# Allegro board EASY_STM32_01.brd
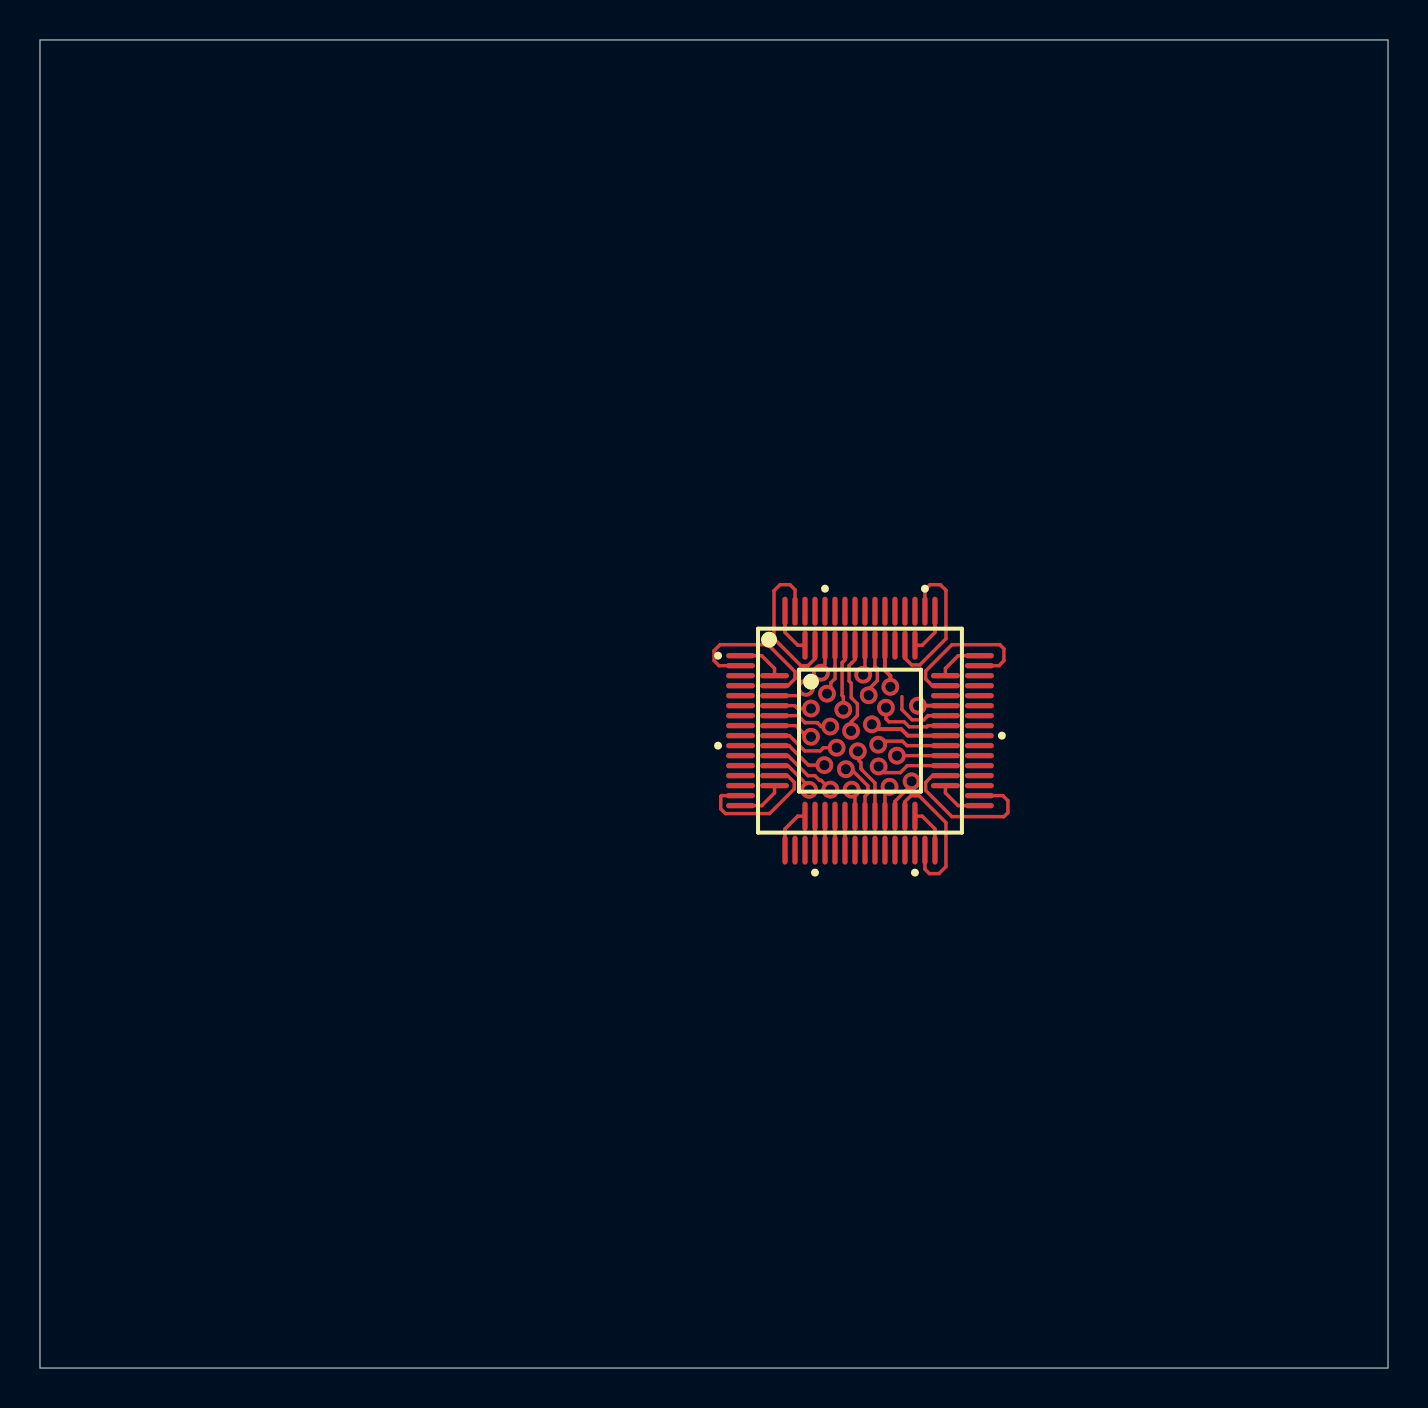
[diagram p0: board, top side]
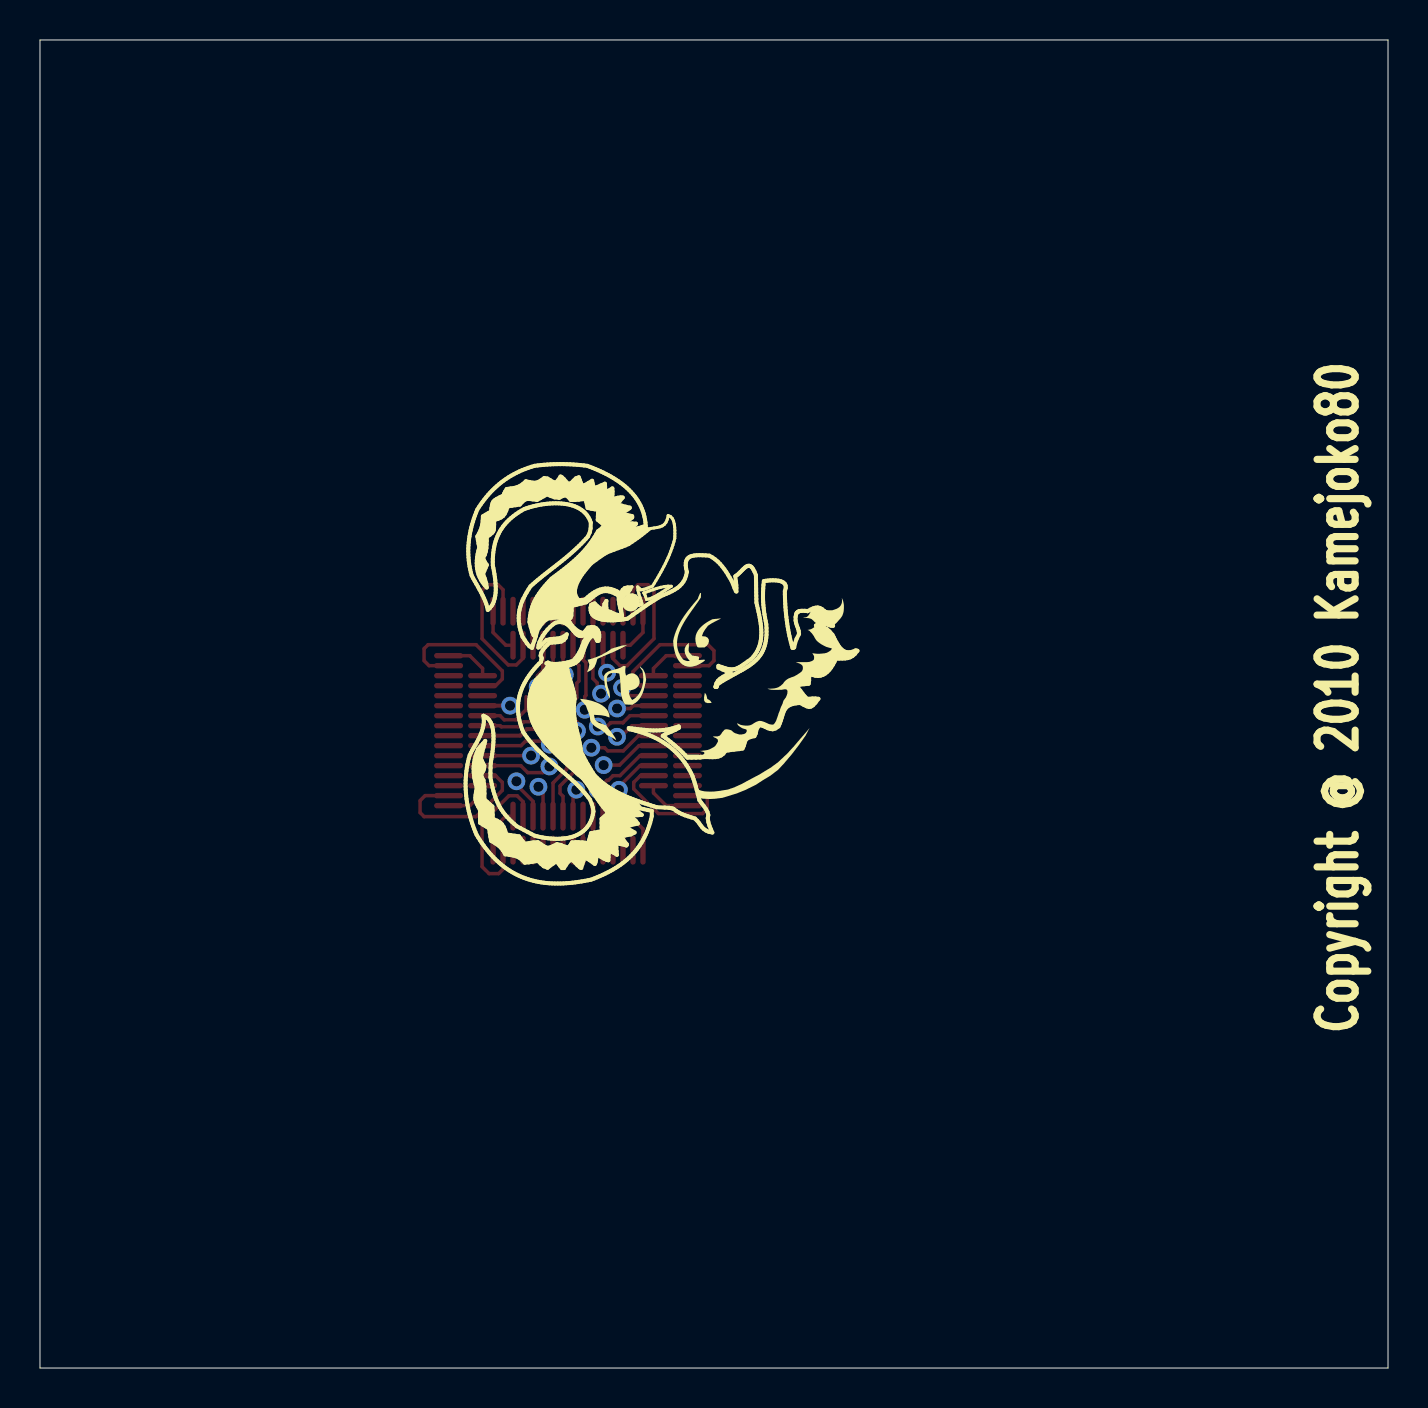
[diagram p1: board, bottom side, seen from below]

Outline 67.44 x 66.42 mm; copper layers: TOP, BOTTOM. Coordinates in mm from the lower left corner of the outline.
Outline path: 0,66.42 0,0 67.44,0 67.44,66.42 0,66.42

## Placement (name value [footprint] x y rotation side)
NOREF  -  []  25.27 25.27 90 bottom
U1  STM32F103RCT6  [LQFP64_MODIFIED]  41.02 31.88 0 top
U2  STM32F100  [LQFP48L]  41.02 31.88 0 top

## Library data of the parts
U1 = STM32F103RCT6_2: User Part Number: pn; Tolerance: RichardLC
U2 = STM32F100_1: User Part Number: pn; Tolerance: RichardLC

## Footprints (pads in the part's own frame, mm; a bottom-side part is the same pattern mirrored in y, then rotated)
LQFP48L
  oval 1.45x0.27 smd: 1(-4.275,2.75) 2(-4.275,2.25) 3(-4.275,1.75) 4(-4.275,1.25) 5(-4.275,0.75) 6(-4.275,0.25) 7(-4.275,-0.25) 8(-4.275,-0.75) 9(-4.275,-1.25) 10(-4.275,-1.75) 11(-4.275,-2.25) 12(-4.275,-2.75) 25(4.275,-2.75) 26(4.275,-2.25) 27(4.275,-1.75) 28(4.275,-1.25) 29(4.275,-0.75) 30(4.275,-0.25) 31(4.275,0.25) 32(4.275,0.75) 33(4.275,1.25) 34(4.275,1.75) 35(4.275,2.25) 36(4.275,2.75)
  oval 0.27x1.45 smd: 13(-2.75,-4.275) 14(-2.25,-4.275) 15(-1.75,-4.275) 16(-1.25,-4.275) 17(-0.75,-4.275) 18(-0.25,-4.275) 19(0.25,-4.275) 20(0.75,-4.275) 21(1.25,-4.275) 22(1.75,-4.275) 23(2.25,-4.275) 24(2.75,-4.275) 37(2.75,4.275) 38(2.25,4.275) 39(1.75,4.275) 40(1.25,4.275) 41(0.75,4.275) 42(0.25,4.275) 43(-0.25,4.275) 44(-0.75,4.275) 45(-1.25,4.275) 46(-1.75,4.275) 47(-2.25,4.275) 48(-2.75,4.275)
LQFP64_MODIFIED
  oval 1.45x0.27 smd: 1(-5.975,3.75) 2(-5.975,3.25) 3(-5.975,2.75) 4(-5.975,2.25) 5(-5.975,1.75) 6(-5.975,1.25) 7(-5.975,0.75) 8(-5.975,0.25) 9(-5.975,-0.25) 10(-5.975,-0.75) 11(-5.975,-1.25) 12(-5.975,-1.75) 13(-5.975,-2.25) 14(-5.975,-2.75) 15(-5.975,-3.25) 16(-5.975,-3.75) 33(5.975,-3.75) 34(5.975,-3.25) 35(5.975,-2.75) 36(5.975,-2.25) 37(5.975,-1.75) 38(5.975,-1.25) 39(5.975,-0.75) 40(5.975,-0.25) 41(5.975,0.25) 42(5.975,0.75) 43(5.975,1.25) 44(5.975,1.75) 45(5.975,2.25) 46(5.975,2.75) 47(5.975,3.25) 48(5.975,3.75)
  oval 0.27x1.45 smd: 17(-3.75,-5.975) 18(-3.25,-5.975) 19(-2.75,-5.975) 20(-2.25,-5.975) 21(-1.75,-5.975) 22(-1.25,-5.975) 23(-0.75,-5.975) 24(-0.25,-5.975) 25(0.25,-5.975) 26(0.75,-5.975) 27(1.25,-5.975) 28(1.75,-5.975) 29(2.25,-5.975) 30(2.75,-5.975) 31(3.25,-5.975) 32(3.75,-5.975) 49(3.75,5.975) 50(3.25,5.975) 51(2.75,5.975) 52(2.25,5.975) 53(1.75,5.975) 54(1.25,5.975) 55(0.75,5.975) 56(0.25,5.975) 57(-0.25,5.975) 58(-0.75,5.975) 59(-1.25,5.975) 60(-1.75,5.975) 61(-2.25,5.975) 62(-2.75,5.975) 63(-3.25,5.975) 64(-3.75,5.975)

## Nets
+3V3: U1.19(VDD_4) U1.32(VDD_1) U1.48(VDD_2) U1.64(VDD_3) U2.24(VDD_1) U2.36(VDD_2) U2.48(VDD_3)
GND: U1.18(VSS_4) U1.31(VSS_1) U1.47(VSS_2) U1.63(VSS_3) U2.23(VSS_1) U2.35(VSS_2) U2.47(VSS_3)
VBAT: U1.1(VBAT) U2.1(VBAT)
VDDA: U1.13(VDDA) U2.9(VDDA)
VSSA: U1.12(VSSA) U2.8(VSSA)
BOOT0: U1.60(BOOT0) U2.44(BOOT0)
NRST: U1.7(NRST) U2.7(NRST)
OSC32_IN: U1.3(PC14/OSC32_IN) U2.3(PC14/OSC32_IN)
OSC32_OUT: U1.4(PC15/OSC32/OUT) U2.4(PC15/OSC32_OUT)
OSC_IN: U1.5(PD0/OSC_IN) U2.5(PD0/OSC_IN)
OSC_OUT: U1.6(PD1/OSC_OUT) U2.6(PD1/OSC_OUT)
PA0: U1.14(PA0-WKUP) U2.10(PA0/WKUP)
PA1: U1.15(PA1) U2.11(PA1)
PA2: U1.16(PA2) U2.12(PA2)
PA3: U1.17(PA3) U2.13(PA3)
PA4: U1.20(PA4) U2.14(PA4)
PA5: U1.21(PA5) U2.15(PA5)
PA6: U1.22(PA6) U2.16(PA6)
PA7: U1.23(PA7) U2.17(PA7)
PA8: U1.41(PA8) U2.29(PA8)
PA9: U1.42(PA9) U2.30(PA9)
PA10: U1.43(PA10) U2.31(PA10)
PA11: U1.44(PA11) U2.32(PA11)
PA12: U1.45(PA12) U2.33(PA12)
PA13: U1.46(PA13) U2.34(PA13)
PA14: U1.49(PA14) U2.37(PA14)
PA15: U1.50(PA15) U2.38(PA15)
PB0: U1.26(PB0) U2.18(PB0)
PB1: U1.27(PB1) U2.19(PB1)
PB2: U1.28(PB2/BOOT1) U2.20(PB2)
PB3: U1.55(PB3) U2.39(PB3)
PB4: U1.56(PB4) U2.40(PB4)
PB5: U1.57(PB5) U2.41(PB5)
PB6: U1.58(PB6) U2.42(PB6)
PB7: U1.59(PB7) U2.43(PB7)
PB8: U1.61(PB8) U2.45(PB8)
PB9: U1.62(PB9) U2.46(PB9)
PB10: U1.29(PB10) U2.21(PB10)
PB11: U1.30(PB11) U2.22(PB11)
PB12: U1.33(PB12) U2.25(PB12)
PB13: U1.34(PB13) U2.26(PB13)
PB14: U1.35(PB14) U2.27(PB14)
PB15: U1.36(PB15) U2.28(PB15)
PC0: U1.8(PC0)
PC1: U1.9(PC1)
PC2: U1.10(PC2)
PC3: U1.11(PC3)
PC4: U1.24(PC4)
PC5: U1.25(PC5)
PC6: U1.37(PC6)
PC7: U1.38(PC7)
PC8: U1.39(PC8)
PC9: U1.40(PC9)
PC10: U1.51(PC10)
PC11: U1.52(PC11)
PC12: U1.53(PC12)
PC13: U1.2(PC13/TAMPER/RTC) U2.2(PC13/TAMPER/RTC)
PD2: U1.54(PD2)

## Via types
v1: diameter 0.889, hole 0.508, TOP to BOTTOM, 26 vias

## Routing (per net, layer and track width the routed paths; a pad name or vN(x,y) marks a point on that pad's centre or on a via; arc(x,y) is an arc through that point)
+3V3: length 7
  TOP w0.175: U1.32 44.77,26.97 44.13,27.6 U2.24 ; U1.48 45.93,35.63 45.3,34.99 U2.36 ; U1.64 37.27,36.79 37.91,36.15 U2.48
GND: length 24.1
  TOP w0.175: U2.35 44.64,34.13 44.31,34.46 44.31,34.86 45.62,36.18 48.02,36.18 48.22,35.98 48.22,35.38 47.97,35.13 U1.47 ; U1.63 37.77,38.93 37.52,39.18 37.02,39.18 36.72,38.88 36.72,36.48 38.07,35.13 38.42,35.13 38.77,35.48 U2.47 ; U2.23 43.27,28.33 43.56,28.62 43.98,28.62 45.32,27.28 45.32,25.08 44.97,24.73 44.49,24.73 44.27,24.95 U1.31
VBAT: length 2.3
  TOP w0.175: U2.1 36.75,34.99 36.11,35.63 U1.1
VDDA: length 3.5
  TOP w0.175: v1(39.54,28.93) 39.07,29.39 39,29.39 38.77,29.63 38.42,29.63 37.42,30.63 U2.9
VSSA: length 2.9
  TOP w0.175: v1(39.24,30.15) 38.44,30.15 37.47,31.13 U2.8
BOOT0: length 3.3
  TOP w0.175: v1(40.19,32.92) 40.19,33.58 40.12,33.64 40.12,35.28 40.27,35.42 U2.44
NRST: length 3.5
  TOP w0.175: U2.7 37.49,31.63 38.26,30.86 39.03,30.86 39.19,31.02 v1(39.85,31.02)
OSC32_IN: length 1.7
  TOP w0.175: U2.3 37.92,33.63 v1(38.32,34.02)
OSC32_OUT: length 1.9
  TOP w0.175: v1(38.57,32.98) 37.91,32.98 37.77,33.13 U2.4
OSC_IN: length 3
  TOP w0.175: U2.5 37.92,32.63 38.27,32.28 38.27,32.28 38.87,32.28 38.88,32.27 38.9,32.27 39.08,32.08 v1(39.53,32.08)
OSC_OUT: length 2.1
  TOP w0.175: U2.6 37.82,32.13 38.27,31.68 38.47,31.68 v1(38.57,31.57)
PA0: length 2.3
  TOP w0.175: U2.10 37.42,30.13 38.48,29.07 v1(38.48,28.92)
PA1: length 7.4
  TOP w0.175: U1.15 34.09,28.63 34.06,28.59 34.06,27.96 34.29,27.73 36.5,27.73 37.73,28.96 37.73,29.29 37.4,29.63 U2.11
PA2: length 2.3
  TOP w0.175: U2.12 36.75,28.76 36.11,28.13 U1.16
PA3: length 2.3
  TOP w0.175: U2.13 37.91,27.6 37.27,26.97 U1.17
PA4: length 1.7
  TOP w0.175: U2.14 U1.20
PA5: length 1.7
  TOP w0.175: U2.15 U1.21
PA6: length 1.7
  TOP w0.175: U2.16 U1.22
PA7: length 1.7
  TOP w0.175: U2.17 U1.23
PA8: length 3.5
  TOP w0.175: v1(41.93,31.18) 42.11,31.35 43.15,31.35 43.37,31.13 U2.29
PA9: length 3.9
  TOP w0.2: v1(41.62,32.19) 41.62,32.19 41.64,32.18 41.66,32.18 41.88,31.96 43.08,31.96 43.41,31.63 U2.30
PA10: length 3.7
  TOP w0.175: v1(42.32,33.03) 42.32,32.47 42.47,32.32 43.23,32.32 43.48,32.07 44.36,32.07 44.42,32.13 U2.31
PA11: length 3.1
  TOP w0.175: 43.12,33.58 43.12,32.93 43.63,32.42 44.21,32.42 44.42,32.63 U2.32
PA12: length 1.4
  TOP w0.2: U2.33 v1(43.92,33.13)
PA14: length 2.3
  TOP w0.175: U1.49 44.77,36.79 44.13,36.15 U2.37
PA15: length 8.2
  TOP w0.175: U2.38 43.27,35.5 43.61,35.16 44.01,35.16 45.32,36.48 45.32,38.9 45.04,39.18 44.52,39.18 44.27,38.93 U1.50
PB0: length 1.4
  TOP w0.175: v1(40.61,28.93) 40.61,28.79 40.77,28.63 U2.18
PB1: length 3
  TOP w0.175: v1(40.31,29.95) 40.34,29.93 40.6,29.93 41.42,29.11 41.42,28.74 41.27,28.59 U2.19
PB2: length 3.6
  TOP w0.175: U2.20 41.77,29.26 41.75,29.28 41.75,29.28 41.12,29.91 41.12,29.93 41.07,29.98 41.07,30.28 40.97,30.38 40.97,30.79 v1(40.91,30.85)
PB4: length 2.2
  TOP w0.2: U2.40 42.27,34.89 42.54,34.62 v1(42.54,34.07)
PB5: length 2.7
  TOP w0.175: v1(41.46,33.65) 41.46,33.95 41.89,34.38 41.89,34.97 41.77,35.09 U2.41
PB6: length 1.5
  TOP w0.175: U2.42 41.27,34.93 41.18,34.84 v1(41.18,34.68)
PB7: length 4.7
  TOP w0.175: v1(40.58,31.86) 40.58,32.31 40.89,32.63 40.89,33.22 40.58,33.53 40.58,34.25 40.48,34.36 40.48,35.13 40.77,35.43 U2.43
PB8: length 2.6
  TOP w0.175: U2.45 39.77,35.07 39.77,35.07 39.77,34.48 39.56,34.27 39.56,34.02 39.37,33.83 v1(39.37,33.73)
PB9: length 1.5
  TOP w0.175: U2.46 39.27,35.22 39.21,35.16 39.21,34.92 v1(39.07,34.77)
PB10: length 1.6
  TOP w0.175: U2.21 42.27,28.83 42.5,29.06 v1(42.5,29.07)
PB11: length 2.1
  TOP w0.175: U2.22 42.77,28.34 43.52,29.09 43.52,29.13 43.6,29.21 v1(43.6,29.34)
PB12: length 2.3
  TOP w0.175: U2.25 45.3,28.76 45.93,28.13 U1.33
PB13: length 8.4
  TOP w0.175: U1.34 48.17,28.63 48.42,28.38 48.42,27.78 48.22,27.58 45.62,27.58 44.31,28.89 44.31,29.29 44.64,29.63 U2.26
PB14: length 3.6
  TOP w0.175: v1(41.95,30.09) 41.98,30.09 42.29,29.78 43.04,29.78 43.38,30.13 U2.27
PB15: length 2.4
  TOP w0.175: U2.28 v1(42.87,30.63)
PC13: length 8.2
  TOP w0.175: U2.2 37.42,34.13 37.77,34.48 37.77,34.83 36.42,36.18 34.02,36.18 33.72,35.88 33.72,35.38 33.97,35.13 U1.2

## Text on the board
Ref Des/Silkscreen Bottom: Copyright @ 2010 Kamejoko80
BODY_CENTER: FIGURE | SIZE | 0.508 | 0.8 | 0.8999 | 0.9144 | 1.0 | 2.4 | DRILL CHART: TOP to BOTTOM | ALL UNITS ARE IN MILLIMETERS | PLATED | QTY | 121 | 14 | 200 | 2 | 4
